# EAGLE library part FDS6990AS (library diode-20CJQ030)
Fairchild's FDS6990AS Dual N-Channel PowerTrench SyncFET General Description: The FDS6990AS is designed to replace a dual SO-8 MOSFET and two Schottky diodes in synchronous DC:DC power supplies. This 30V MOSFET is designed to maximize power conversion efficiency, providing a low RDS(ON) and low gate charge. Each MOSFET includes integrated Schottky diodes using Fairchild?s monolithic SyncFET technology. The performance of the FDS6990AS as the low-side switch in a synchronous rectifier is similar to the performance of the FDS6990A in parallel with a Schottky diode. Features: 7.5 A, 30 V. RDS(ON) = 22 mOhm @ VGS = 10 V RDS(ON) = 28 mOhm @ VGS = 4.5 V Includes SyncFET Schottky diode Low gate charge (10nC typical) High performance trench technology for extremely low RDS(ON) High power and current handling capability Application: DC/DC converter Motor drives Please send any comments to: messi@users.sourceforge.net
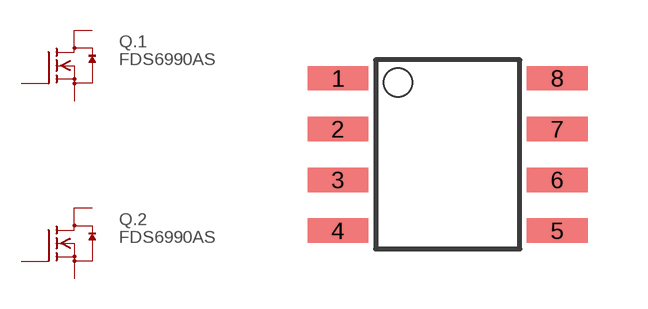
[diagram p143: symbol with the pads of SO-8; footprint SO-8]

Designator prefix Q; gates .1=IGFET-4-N-CH .2=IGFET-4-N-CH

## FDS6990AS  [SO-8]
1  .2:S  pas
2  .2:G  pas
3  .1:S  pas
4  .1:G  pas
5  .1:D  pas
6  .1:D  pas
7  .2:D  pas
8  .2:D  pas

## Footprint SO-8 (pad centres in mm)
small outline
smd 1.524 x 0.61: 1 -2.743,1.27; 2 -2.743,0; 3 -2.743,-1.27; 4 -2.743,-2.54; 5 2.743,-2.54; 6 2.743,-1.27; 7 2.743,0; 8 2.743,1.27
